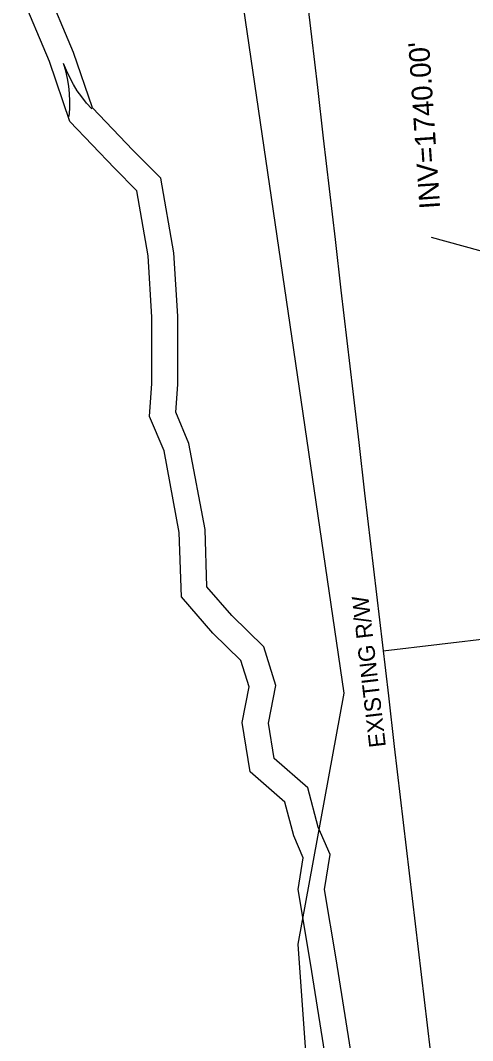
# Model space of a CAD drawing. Extents: x 472260 to 482161, y 489063 to 507124.
# Drawn here: x 477964.3 to 478051.6, y 497778.2 to 497975.5 of the extents above; entities that cross this region are included whole.
import ezdxf

# ---------------------------------------------------------------- set-up
doc = ezdxf.new("R2010")
doc.units = 0
for name, color, linetype in [('Exist Other Culture AG Tank Leader', 7, 'Continuous'), ('Exist Structure Minor Drop Inlet Cogo Elevation', 7, 'Continuous'), ('Exist Structure Minor Pipes CMP 15 Inch Cogo Comment', 7, 'Continuous'), ('Exist Structure Minor Pipes CMP 15 Inch Cogo Point CELL', 7, 'Continuous'), ('Exist Structure Minor Pipes HDPE 12 Inch Text', 7, 'Continuous'), ('Prop Drainage Structure Pipe RCP 24in Class III', 7, 'Continuous'), ('Prop Erosion Rip Rap Pad at Outlet Label', 7, 'Continuous'), ('Scratch_Level_8', 7, 'Continuous')]:
    doc.layers.add(name, color=color, linetype=linetype)

msp = doc.modelspace()

# ---------------------------------------------------------------- linework, layer by layer
at = {"layer": 'Exist Other Culture AG Tank Leader'}
msp.add_line((478111.17, 497914.83), (478043.71, 497933.5), dxfattribs=at)
at = {"layer": 'Exist Structure Minor Drop Inlet Cogo Elevation'}
msp.add_arc((592937.27, 511299.31), 115686.96, 186.405023, 186.7177067, dxfattribs=at)
at = {"layer": 'Exist Structure Minor Pipes CMP 15 Inch Cogo Comment'}
msp.add_line((478034.33, 497853.59), (478084.55, 497859.46), dxfattribs=at)
at = {"layer": 'Prop Drainage Structure Pipe RCP 24in Class III'}
for points in [[(478028.49, 497773.7), (478025.26, 497794.01), (478023, 497807.43), (478024.11, 497814.17), (478021.81, 497819.46), (478019.8, 497827.09), (478013.33, 497832.76), (478012.18, 497839.62), (478013.6, 497846.86), (478011.29, 497854.37), (478005.11, 497860.42), (478000.32, 497865.94), (477999.96, 497877.03), (477996.85, 497893.67), (477994.29, 497899.75), (477994.67, 497905.08), (477994.7, 497918.26), (477993.93, 497930.56), (477991.44, 497944.94), (477986.04, 497950.37), (477978.21, 497958.57), (477974.57, 497969.27), (477969.11, 497982.35)], [(478023.54, 497772.95), (478020.33, 497793.2), (478017.93, 497807.42), (478018.93, 497813.53), (478017.07, 497817.82), (478015.35, 497824.34), (478008.69, 497830.17), (478007.1, 497839.69), (478008.45, 497846.59), (478006.88, 497851.69), (478001.46, 497856.99), (477995.39, 497864), (477994.97, 497876.48), (477992.03, 497892.22), (477989.22, 497898.91), (477989.67, 497905.27), (477989.7, 497918.11), (477988.95, 497929.97), (477986.78, 497942.53), (477982.46, 497946.88), (477973.84, 497955.92), (477969.89, 497967.5), (477964.3, 497980.89)]]:
    msp.add_lwpolyline(points, dxfattribs=at)
at = {"layer": 'Prop Erosion Rip Rap Pad at Outlet Label'}
msp.add_lwpolyline([(477979.45, 498191.25), (477993.64, 498099.1), (478005.17, 497992.72), (478026.78, 497845.41), (478017.87, 497796.88), (478023.44, 497718.17), (478022.43, 497688.31), (478027.96, 497668.21)], dxfattribs=at)
at = {"layer": 'Scratch_Level_8'}
msp.add_line((477974.28, 497962.38), (477974.28, 497962.38), dxfattribs=at)
for points in [[(477978.06, 497958.39), (477977.06, 497959.46), (477976.16, 497960.66), (477975.29, 497961.86), (477974.54, 497963.09), (477973.84, 497964.4), (477973.2, 497965.75), (477972.65, 497967.11)], [(477973.74, 497956.91), (477973.87, 497958.37), (477973.84, 497959.87), (477973.8, 497961.34), (477973.64, 497962.78), (477973.39, 497964.24), (477973.06, 497965.7), (477972.65, 497967.11)]]:
    msp.add_lwpolyline(points, dxfattribs=at)

# ---------------------------------------------------------------- texts
at = {"layer": 'Exist Structure Minor Pipes CMP 15 Inch Cogo Point CELL'}
msp.add_text('EXISTING R/W', height=3.2, rotation=96.6756, dxfattribs=at).set_placement((478034.88, 497835.08))
at = {"layer": 'Exist Structure Minor Pipes HDPE 12 Inch Text'}
msp.add_text("INV=1740.00'", height=4, rotation=93.8758, dxfattribs=at).set_placement((478045.37, 497939.14))

doc.saveas('drawing.dxf')
